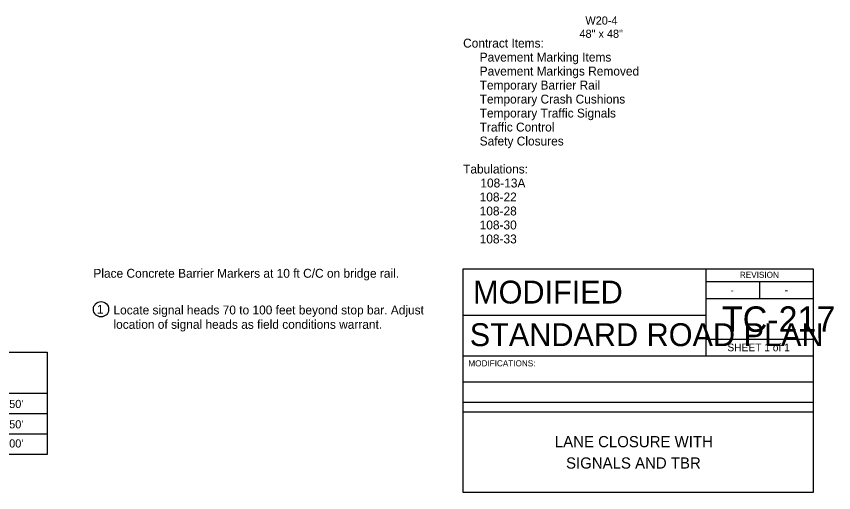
# Model space of a CAD drawing. Extents: x 10124 to 16850, y 7924 to 12166.
# Drawn here: x 15243 to 16850, y 7924 to 8860 of the extents above; entities that cross this region are included whole.
import ezdxf

# ---------------------------------------------------------------- set-up
doc = ezdxf.new("R2010")
doc.units = 0
for name, color, linetype in [('dsnStdBlock', 7, 'Continuous'), ('dsnStdBlockModified', 7, 'Continuous'), ('dsnStdBlockNotModified', 7, 'Continuous'), ('Level 1', 7, 'Continuous'), ('Level 2', 7, 'Continuous'), ('Level 3', 7, 'Continuous')]:
    doc.layers.add(name, color=color, linetype=linetype)

msp = doc.modelspace()

# ---------------------------------------------------------------- linework, layer by layer
at = {"layer": 'dsnStdBlock'}
for p, q in [((16122.9, 8363.5), (16122.9, 8363.5)), ((16598.4, 8364), (16598.4, 8272.7)), ((16598.4, 8339.1), (16809.3, 8339.1)), ((16703.8, 8339.1), (16703.8, 8305.9)), ((16598.4, 8305.9), (16809.3, 8305.9)), ((16598.4, 8272.7), (16598.4, 8192.7)), ((16809.3, 8224.9), (16598.4, 8224.9)), ((16121.3, 8192.7), (16809.3, 8192.7)), ((16121.3, 8082.7), (16809.3, 8082.7))]:
    msp.add_line(p, q, dxfattribs=at)
msp.add_lwpolyline([(16121.3, 8364), (16809.3, 8364), (16809.3, 7924), (16121.3, 7924)], close=True, dxfattribs=at)
at = {"layer": 'dsnStdBlockNotModified'}
for p, q in [((16121.3, 8272.7), (16598.4, 8272.7)), ((16121.3, 8141.7), (16809.3, 8141.7)), ((16121.3, 8101.7), (16809.3, 8101.7))]:
    msp.add_line(p, q, dxfattribs=at)
at = {"layer": 'Level 2'}
for p, q in [((14963.7, 8200.3), (15303.7, 8200.3)), ((15303.7, 8200.3), (15303.7, 7999)), ((15303.7, 8119), (14963.7, 8119)), ((15303.7, 8079), (14963.7, 8079)), ((15303.7, 8039), (14963.7, 8039)), ((15303.7, 7999), (14963.7, 7999))]:
    msp.add_line(p, q, dxfattribs=at)
msp.add_circle((15409.5, 8284.5), 15, dxfattribs=at)

# ---------------------------------------------------------------- texts
at = {"layer": 'dsnStdBlock'}
for s, height, p in [('REVISION', 12, (16665.3, 8346.2)), ('-', 15, (16646.8, 8314.6)), ('-', 15, (16753.4, 8315.1)), ('TC-217', 50, (16630, 8240.2)), ('STANDARD ROAD PLAN', 45.001, (16134.3, 8212.1)), ('SHEET 1 of 1', 15, (16640.8, 8202)), ('LANE CLOSURE WITH', 22, (16301.6, 8013.3)), ('SIGNALS AND TBR', 22, (16323.6, 7971.3))]:
    msp.add_text(s, height=height, dxfattribs=at).set_placement(p)
at = {"layer": 'dsnStdBlockModified'}
for s, height, p in [('MODIFIED', 45, (16140.9, 8295.8)), ('MODIFICATIONS:', 12, (16131.6, 8172.3))]:
    msp.add_text(s, height=height, dxfattribs=at).set_placement(p)
at = {"layer": 'Level 1'}
msp.add_text('Place Concrete Barrier Markers at 10 ft C/C on bridge rail.', height=17.5, dxfattribs=at).set_placement((15394.5, 8346.5))
at = {"layer": 'Level 2'}
for s, height, p in [('W20-4', 16, (16361.7, 8844.2)), ('48" x 48"', 16, (16350, 8818.2)), ('Contract Items:', 17.5, (16121.3, 8799)), ('     Pavement Marking Items', 17.5, (16121.3, 8771.5)), ('     Pavement Markings Removed', 17.5, (16121.3, 8744)), ('     Temporary Barrier Rail', 17.5, (16121.3, 8716.5)), ('     Temporary Crash Cushions', 17.5, (16121.3, 8689)), ('     Temporary Traffic Signals', 17.5, (16121.3, 8661.5)), ('     Traffic Control', 17.5, (16121.3, 8634)), ('     Safety Closures', 17.5, (16121.3, 8606.5)), ('Tabulations:', 17.5, (16121.3, 8551.5)), ('108-13A', 17.5, (16155.2, 8524)), ('     108-22', 17.5, (16121.3, 8496.5)), ('     108-28', 17.5, (16121.3, 8469)), ('     108-30', 17.5, (16121.3, 8441.5)), ('     108-33', 17.5, (16121.3, 8414)), ('1', 17.5, (15401.4, 8275.7)), ('Locate signal heads 70 to 100 feet beyond stop bar. Adjust ', 17.5, (15434, 8274.4)), ('location of signal heads as field conditions warrant.', 17.5, (15434, 8246.1))]:
    msp.add_text(s, height=height, dxfattribs=at).set_placement(p)
at = {"layer": 'Level 3'}
for s, p in [("250'", (15217.1, 8090.4)), ("350'", (15217.1, 8050.4)), ("500'", (15217.1, 8012.8))]:
    msp.add_text(s, height=16, dxfattribs=at).set_placement(p)

doc.saveas('drawing.dxf')
